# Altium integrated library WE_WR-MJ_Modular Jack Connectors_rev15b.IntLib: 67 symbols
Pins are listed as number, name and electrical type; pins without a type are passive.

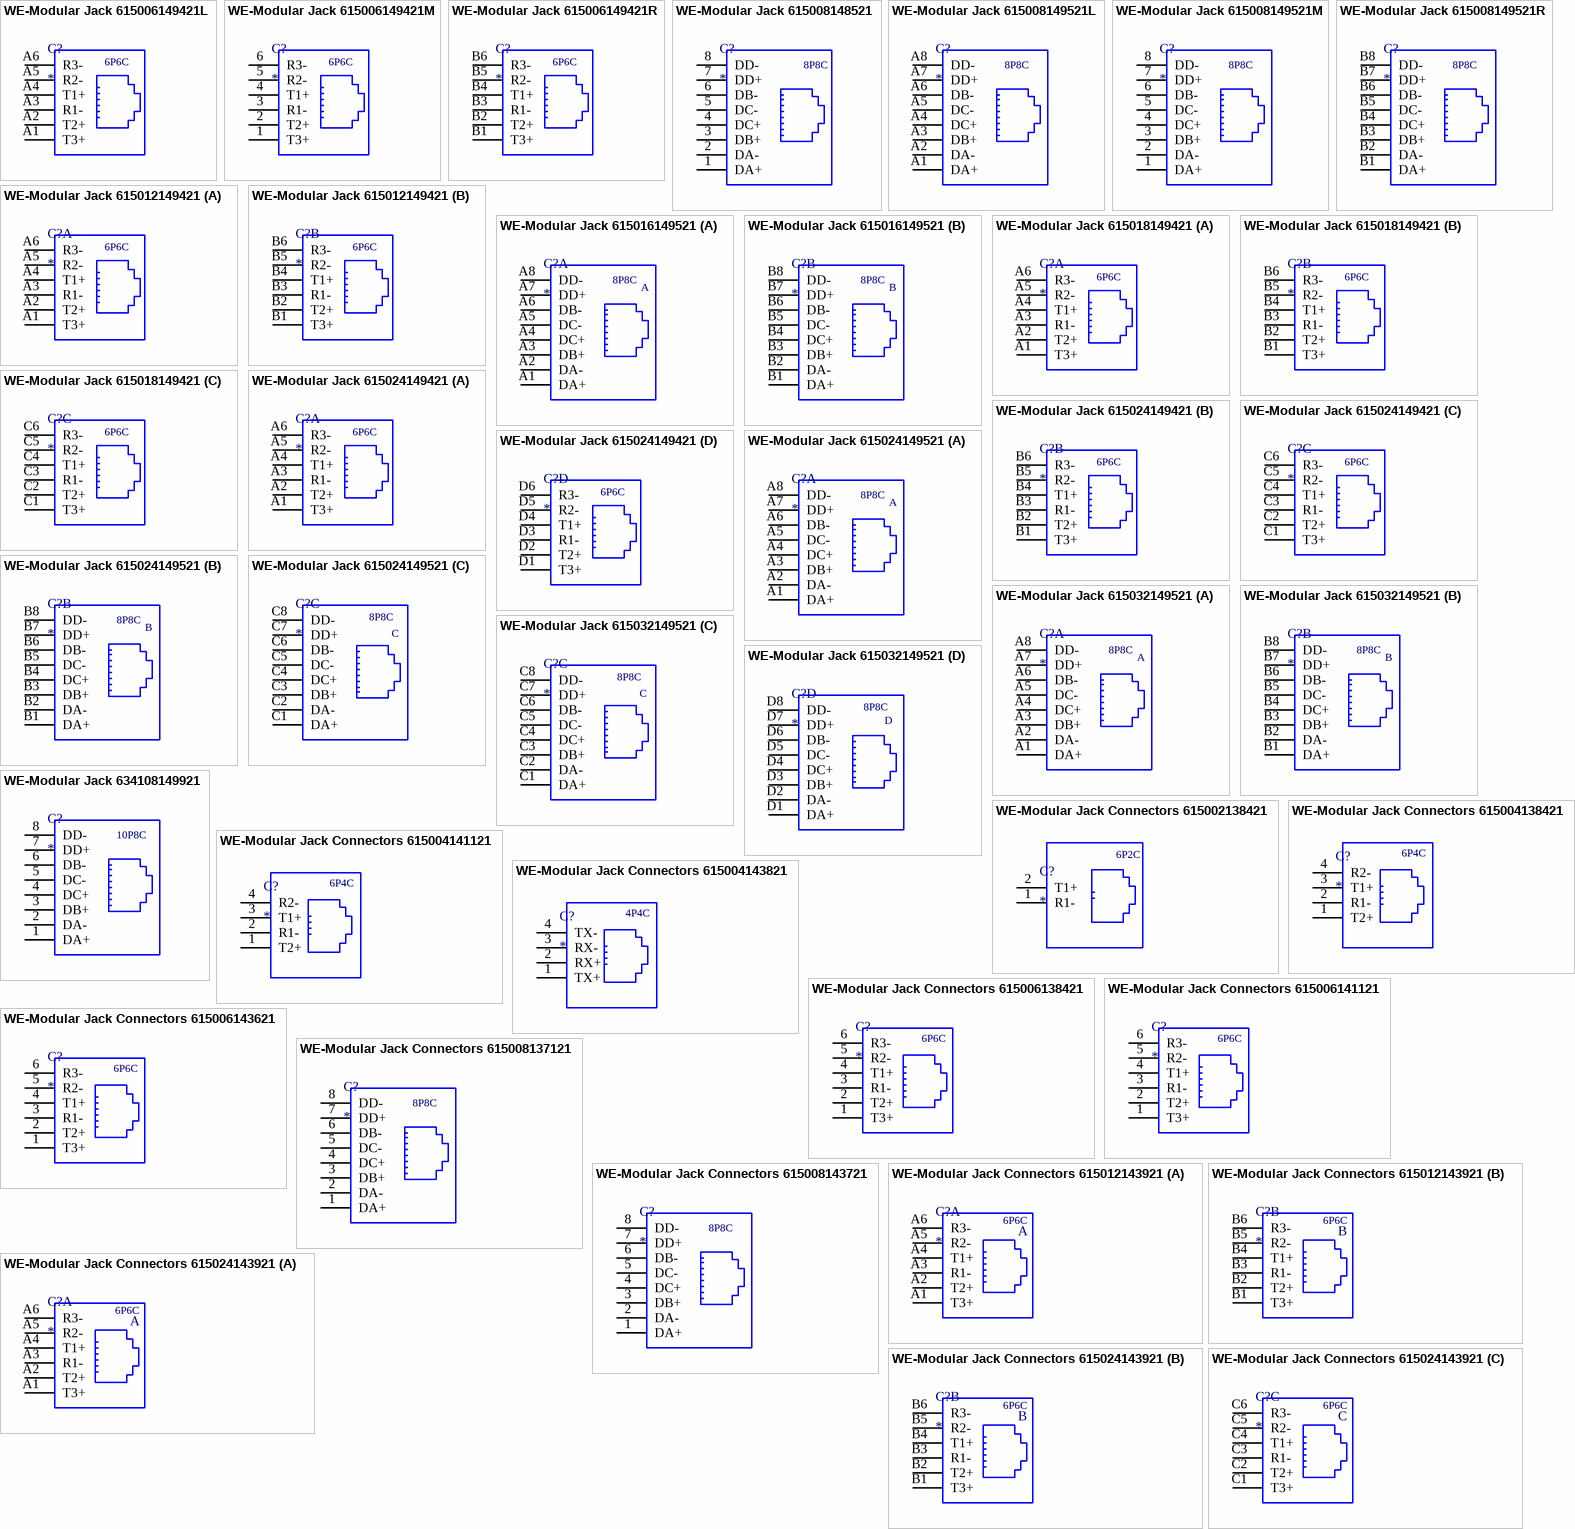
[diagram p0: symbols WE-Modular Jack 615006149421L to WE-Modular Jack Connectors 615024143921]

## WE-Modular Jack 615006149421L
designator C?
WR-MJ_Modular Jack_Tab UP_6P6C; Manufacturer: Würth Elektronik eiSos GmbH; partNo: 615006149421L; ComponentLink1 Description: Manufacturer; ComponentLink2 Description: Datasheet; NoPins: 6
footprint 615006149421L
pins: A1 T3+, A2 T2+, A3 R1-, A4 T1+, A5 R2-, A6 R3-

## WE-Modular Jack 615006149421M
designator C?
WR-MJ_Modular Jack_Tab UP_6P6C; Manufacturer: Würth Elektronik eiSos GmbH; partNo: 615006149421M; ComponentLink1 Description: Manufacturer; ComponentLink2 Description: Datasheet; NoPins: 6
footprint 615006149421M
pins: 1 T3+, 2 T2+, 3 R1-, 4 T1+, 5 R2-, 6 R3-

## WE-Modular Jack 615006149421R
designator C?
WR-MJ_Modular Jack_Tab UP_6P6C; Manufacturer: Würth Elektronik eiSos GmbH; partNo: 615006149421R; ComponentLink1 Description: Manufacturer; ComponentLink2 Description: Datasheet; NoPins: 6
footprint 615006149421R
pins: B1 T3+, B2 T2+, B3 R1-, B4 T1+, B5 R2-, B6 R3-

## WE-Modular Jack 615008148521
designator C?
WR-MJ_Modular Jacks_Plastic_8P8C; Manufacturer: Würth Elektronik eiSos GmbH; partNo: 615008148521; ComponentLink1 Description: Manufacturer; ComponentLink2 Description: Datasheet; NoPins: 8
footprint 615008148521
pins: 1 DA+, 2 DA-, 3 DB+, 4 DC+, 5 DC-, 6 DB-, 7 DD+, 8 DD-

## WE-Modular Jack 615008149521L
designator C?
WR-MJ_Modular Jack_Tab UP_8P8C; Manufacturer: Würth Elektronik eiSos GmbH; partNo: 615008149521L; ComponentLink1 Description: Manufacturer; ComponentLink2 Description: Datasheet; NoPins: 8
footprint 615008149521L
pins: A1 DA+, A2 DA-, A3 DB+, A4 DC+, A5 DC-, A6 DB-, A7 DD+, A8 DD-

## WE-Modular Jack 615008149521M
designator C?
WR-MJ_Modular Jack_Tab UP_8P8C; Manufacturer: Würth Elektronik eiSos GmbH; partNo: 615008149521M; ComponentLink1 Description: Manufacturer; ComponentLink2 Description: Datasheet; NoPins: 8
footprint 615008149521M
pins: 1 DA+, 2 DA-, 3 DB+, 4 DC+, 5 DC-, 6 DB-, 7 DD+, 8 DD-

## WE-Modular Jack 615008149521R
designator C?
WR-MJ_Modular Jack_Tab UP_8P8C; Manufacturer: Würth Elektronik eiSos GmbH; partNo: 615008149521R; ComponentLink1 Description: Manufacturer; ComponentLink2 Description: Datasheet; NoPins: 8
footprint 615008149521R
pins: B1 DA+, B2 DA-, B3 DB+, B4 DC+, B5 DC-, B6 DB-, B7 DD+, B8 DD-

## WE-Modular Jack 615012149421
designator C?
WR-MJ_Modular Jack_Tab UP_6P6C; Manufacturer: Würth Elektronik eiSos GmbH; partNo: 615012149421; ComponentLink1 Description: Manufacturer; ComponentLink2 Description: Datasheet; NoPins: 12
footprint 615012149421
part A pins: A1 T3+, A2 T2+, A3 R1-, A4 T1+, A5 R2-, A6 R3-
part B pins: B1 T3+, B2 T2+, B3 R1-, B4 T1+, B5 R2-, B6 R3-

## WE-Modular Jack 615016149521
designator C?
WR-MJ_Modular Jack_Tab UP_8P8C; Manufacturer: Würth Elektronik eiSos GmbH; partNo: 615016149521; ComponentLink1 Description: Manufacturer; ComponentLink2 Description: Datasheet; NoPins: 16
footprint 615016149521
part A pins: A1 DA+, A2 DA-, A3 DB+, A4 DC+, A5 DC-, A6 DB-, A7 DD+, A8 DD-
part B pins: B1 DA+, B2 DA-, B3 DB+, B4 DC+, B5 DC-, B6 DB-, B7 DD+, B8 DD-

## WE-Modular Jack 615018149421
designator C?
WR-MJ_Modular Jack_Tab UP_6P6C; Manufacturer: Würth Elektronik eiSos GmbH; partNo: 615018149421; ComponentLink1 Description: Manufacturer; ComponentLink2 Description: Datasheet; NoPins: 18
footprint 615018149421
part A pins: A1 T3+, A2 T2+, A3 R1-, A4 T1+, A5 R2-, A6 R3-
part B pins: B1 T3+, B2 T2+, B3 R1-, B4 T1+, B5 R2-, B6 R3-
part C pins: C1 T3+, C2 T2+, C3 R1-, C4 T1+, C5 R2-, C6 R3-

## WE-Modular Jack 615024149421
designator C?
WR-MJ_Modular Jack_Tab UP_6P6C; Manufacturer: Würth Elektronik eiSos GmbH; partNo: 615024149421; ComponentLink1 Description: Manufacturer; ComponentLink2 Description: Datasheet; NoPins: 24
footprint 615024149421
part A pins: A1 T3+, A2 T2+, A3 R1-, A4 T1+, A5 R2-, A6 R3-
part B pins: B1 T3+, B2 T2+, B3 R1-, B4 T1+, B5 R2-, B6 R3-
part C pins: C1 T3+, C2 T2+, C3 R1-, C4 T1+, C5 R2-, C6 R3-
part D pins: D1 T3+, D2 T2+, D3 R1-, D4 T1+, D5 R2-, D6 R3-

## WE-Modular Jack 615024149521
designator C?
WR-MJ_Modular Jack_Tab UP_8P8C; Manufacturer: Würth Elektronik eiSos GmbH; partNo: 615024149521; ComponentLink1 Description: Manufacturer; ComponentLink2 Description: Datasheet; NoPins: 24
footprint 615024149521
part A pins: A1 DA+, A2 DA-, A3 DB+, A4 DC+, A5 DC-, A6 DB-, A7 DD+, A8 DD-
part B pins: B1 DA+, B2 DA-, B3 DB+, B4 DC+, B5 DC-, B6 DB-, B7 DD+, B8 DD-
part C pins: C1 DA+, C2 DA-, C3 DB+, C4 DC+, C5 DC-, C6 DB-, C7 DD+, C8 DD-

## WE-Modular Jack 615032149521
designator C?
WR-MJ_Modular Jack_Tab UP_8P8C; Manufacturer: Würth Elektronik eiSos GmbH; partNo: 615032149521; ComponentLink1 Description: Manufacturer; ComponentLink2 Description: Datasheet; NoPins: 32
footprint 615032149521
part A pins: A1 DA+, A2 DA-, A3 DB+, A4 DC+, A5 DC-, A6 DB-, A7 DD+, A8 DD-
part B pins: B1 DA+, B2 DA-, B3 DB+, B4 DC+, B5 DC-, B6 DB-, B7 DD+, B8 DD-
part C pins: C1 DA+, C2 DA-, C3 DB+, C4 DC+, C5 DC-, C6 DB-, C7 DD+, C8 DD-
part D pins: D1 DA+, D2 DA-, D3 DB+, D4 DC+, D5 DC-, D6 DB-, D7 DD+, D8 DD-

## WE-Modular Jack 634108149921
designator C?
WR-MJ_Modular Jack_Tab DOWN_10P8C; Manufacturer: Würth Elektronik eiSos GmbH; partNo: 634108149921; ComponentLink1 Description: Manufacturer; ComponentLink2 Description: Datasheet; NoPins: 8
footprint 634108149921
pins: 1 DA+, 2 DA-, 3 DB+, 4 DC+, 5 DC-, 6 DB-, 7 DD+, 8 DD-

## WE-Modular Jack Connectors 615002138421
designator C?
WR-COM Modular Jack Horizontal Plastic 1x1 TH    6P2C Tab Up; Manufacturer: Würth Elektronik eiSos GmbH; partNo: 615002138421; ComponentLink1 Description: Manufacturer; ComponentLink2 Description: Datasheet; NoPins: 2
footprint 615002138421
pins: 1 R1-, 2 T1+

## WE-Modular Jack Connectors 615004138421
designator C?
WR-COM Modular Jack Horizontal Plastic 1x1 TH    6P4C Tab Up; Manufacturer: Würth Elektronik eiSos GmbH; partNo: 615004138421; ComponentLink1 Description: Manufacturer; ComponentLink2 Description: Datasheet; NoPins: 4
footprint 615004138421
pins: 1 T2+, 2 R1-, 3 T1+, 4 R2-

## WE-Modular Jack Connectors 615004141121
designator C?
WR-COM Modular Jack Horizontal Plastic 1x1 TH    6P4C Tab Down; Manufacturer: Würth Elektronik eiSos GmbH; partNo: 615004141121; ComponentLink1 Description: Manufacturer; ComponentLink2 Description: Datasheet; NoPins: 4
footprint 615004141121
pins: 1 T2+, 2 R1-, 3 T1+, 4 R2-

## WE-Modular Jack Connectors 615004143821
designator C?
WR-COM Modular Jack Horizontal Plastic 1x1 TH    4P4C Tab Up; Manufacturer: Würth Elektronik eiSos GmbH; partNo: 615004143821; ComponentLink1 Description: Manufacturer; ComponentLink2 Description: Datasheet; NoPins: 4
footprint 615004143821
pins: 1 TX+, 2 RX+, 3 RX-, 4 TX-

## WE-Modular Jack Connectors 615006138421
designator C?
WR-COM Modular Jack Horizontal Plastic 1x1 TH  6P6C Tab Up; Manufacturer: Würth Elektronik eiSos GmbH; partNo: 615006138421; ComponentLink1 Description: Manufacturer; ComponentLink2 Description: Datasheet; NoPins: 6
footprint 615006138421
pins: 1 T3+, 2 T2+, 3 R1-, 4 T1+, 5 R2-, 6 R3-

## WE-Modular Jack Connectors 615006141121
designator C?
WR-COM Modular Jack Horizontal Plastic 1x1 TH    6P6C Tab Down; Manufacturer: Würth Elektronik eiSos GmbH; partNo: 615006141121; ComponentLink1 Description: Manufacturer; ComponentLink2 Description: Datasheet; NoPins: 6
footprint 615006141121
pins: 1 T3+, 2 T2+, 3 R1-, 4 T1+, 5 R2-, 6 R3-

## WE-Modular Jack Connectors 615006143621
designator C?
WR-COM Modular Jack Horizontal Plastic 1x1 TH    6P6C Tab Down; Manufacturer: Würth Elektronik eiSos GmbH; partNo: 615006143621; ComponentLink1 Description: Manufacturer; ComponentLink2 Description: Datasheet; NoPins: 6
footprint 615006143621
pins: 1 T3+, 2 T2+, 3 R1-, 4 T1+, 5 R2-, 6 R3-

## WE-Modular Jack Connectors 615008137121
designator C?
WR-COM Modular Jack RJ45 Horizontal Tab down; Manufacturer: Würth Elektronik eiSos GmbH; partNo: 615008137121; ComponentLink1 Description: Manufacturer; ComponentLink2 Description: Datasheet; NoPins: 8
footprint 615008137121
pins: 1 DA+, 2 DA-, 3 DB+, 4 DC+, 5 DC-, 6 DB-, 7 DD+, 8 DD-

## WE-Modular Jack Connectors 615008143721
designator C?
WR-COM Modular Jack Horizontal Plastic 1x1 TH    8P8C Tab Down; Manufacturer: Würth Elektronik eiSos GmbH; partNo: 615008143721; ComponentLink1 Description: Manufacturer; ComponentLink2 Description: Datasheet; NoPins: 8
footprint 615008143721
pins: 1 DA+, 2 DA-, 3 DB+, 4 DC+, 5 DC-, 6 DB-, 7 DD+, 8 DD-

## WE-Modular Jack Connectors 615012143921
designator C?
WR-COM Modular Jack Horizontal Plastic 1x2 TH    6P6C Tab Up; Manufacturer: Würth Elektronik eiSos GmbH; partNo: 615012143921; ComponentLink1 Description: Manufacturer; ComponentLink2 Description: Datasheet; NoPins: 12
footprint 615012143921
part A pins: A1 T3+, A2 T2+, A3 R1-, A4 T1+, A5 R2-, A6 R3-
part B pins: B1 T3+, B2 T2+, B3 R1-, B4 T1+, B5 R2-, B6 R3-

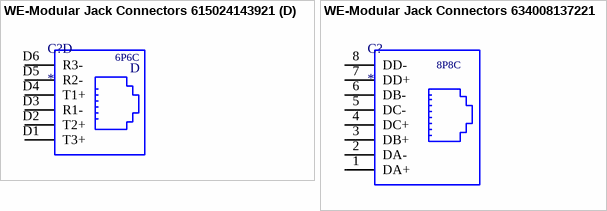
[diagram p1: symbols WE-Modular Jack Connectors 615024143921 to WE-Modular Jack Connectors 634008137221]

## WE-Modular Jack Connectors 615024143921
designator C?
WR-COM Modular Jack Horizontal Plastic 1x4 TH    6P6C Tab Up; Manufacturer: Würth Elektronik eiSos GmbH; partNo: 615024143921; ComponentLink1 Description: Manufacturer; ComponentLink2 Description: Datasheet; NoPins: 24
footprint 615024143921
part A pins: A1 T3+, A2 T2+, A3 R1-, A4 T1+, A5 R2-, A6 R3-
part B pins: B1 T3+, B2 T2+, B3 R1-, B4 T1+, B5 R2-, B6 R3-
part C pins: C1 T3+, C2 T2+, C3 R1-, C4 T1+, C5 R2-, C6 R3-
part D pins: D1 T3+, D2 T2+, D3 R1-, D4 T1+, D5 R2-, D6 R3-

## WE-Modular Jack Connectors 634008137221
designator C?
WR-COM Modular Jack RJ45 Horizontal SMT Tab down; Manufacturer: Würth Elektronik eiSos GmbH; partNo: 634008137221; ComponentLink1 Description: Manufacturer; ComponentLink2 Description: Datasheet; NoPins: 8
footprint 634008137221
pins: 1 DA+, 2 DA-, 3 DB+, 4 DC+, 5 DC-, 6 DB-, 7 DD+, 8 DD-


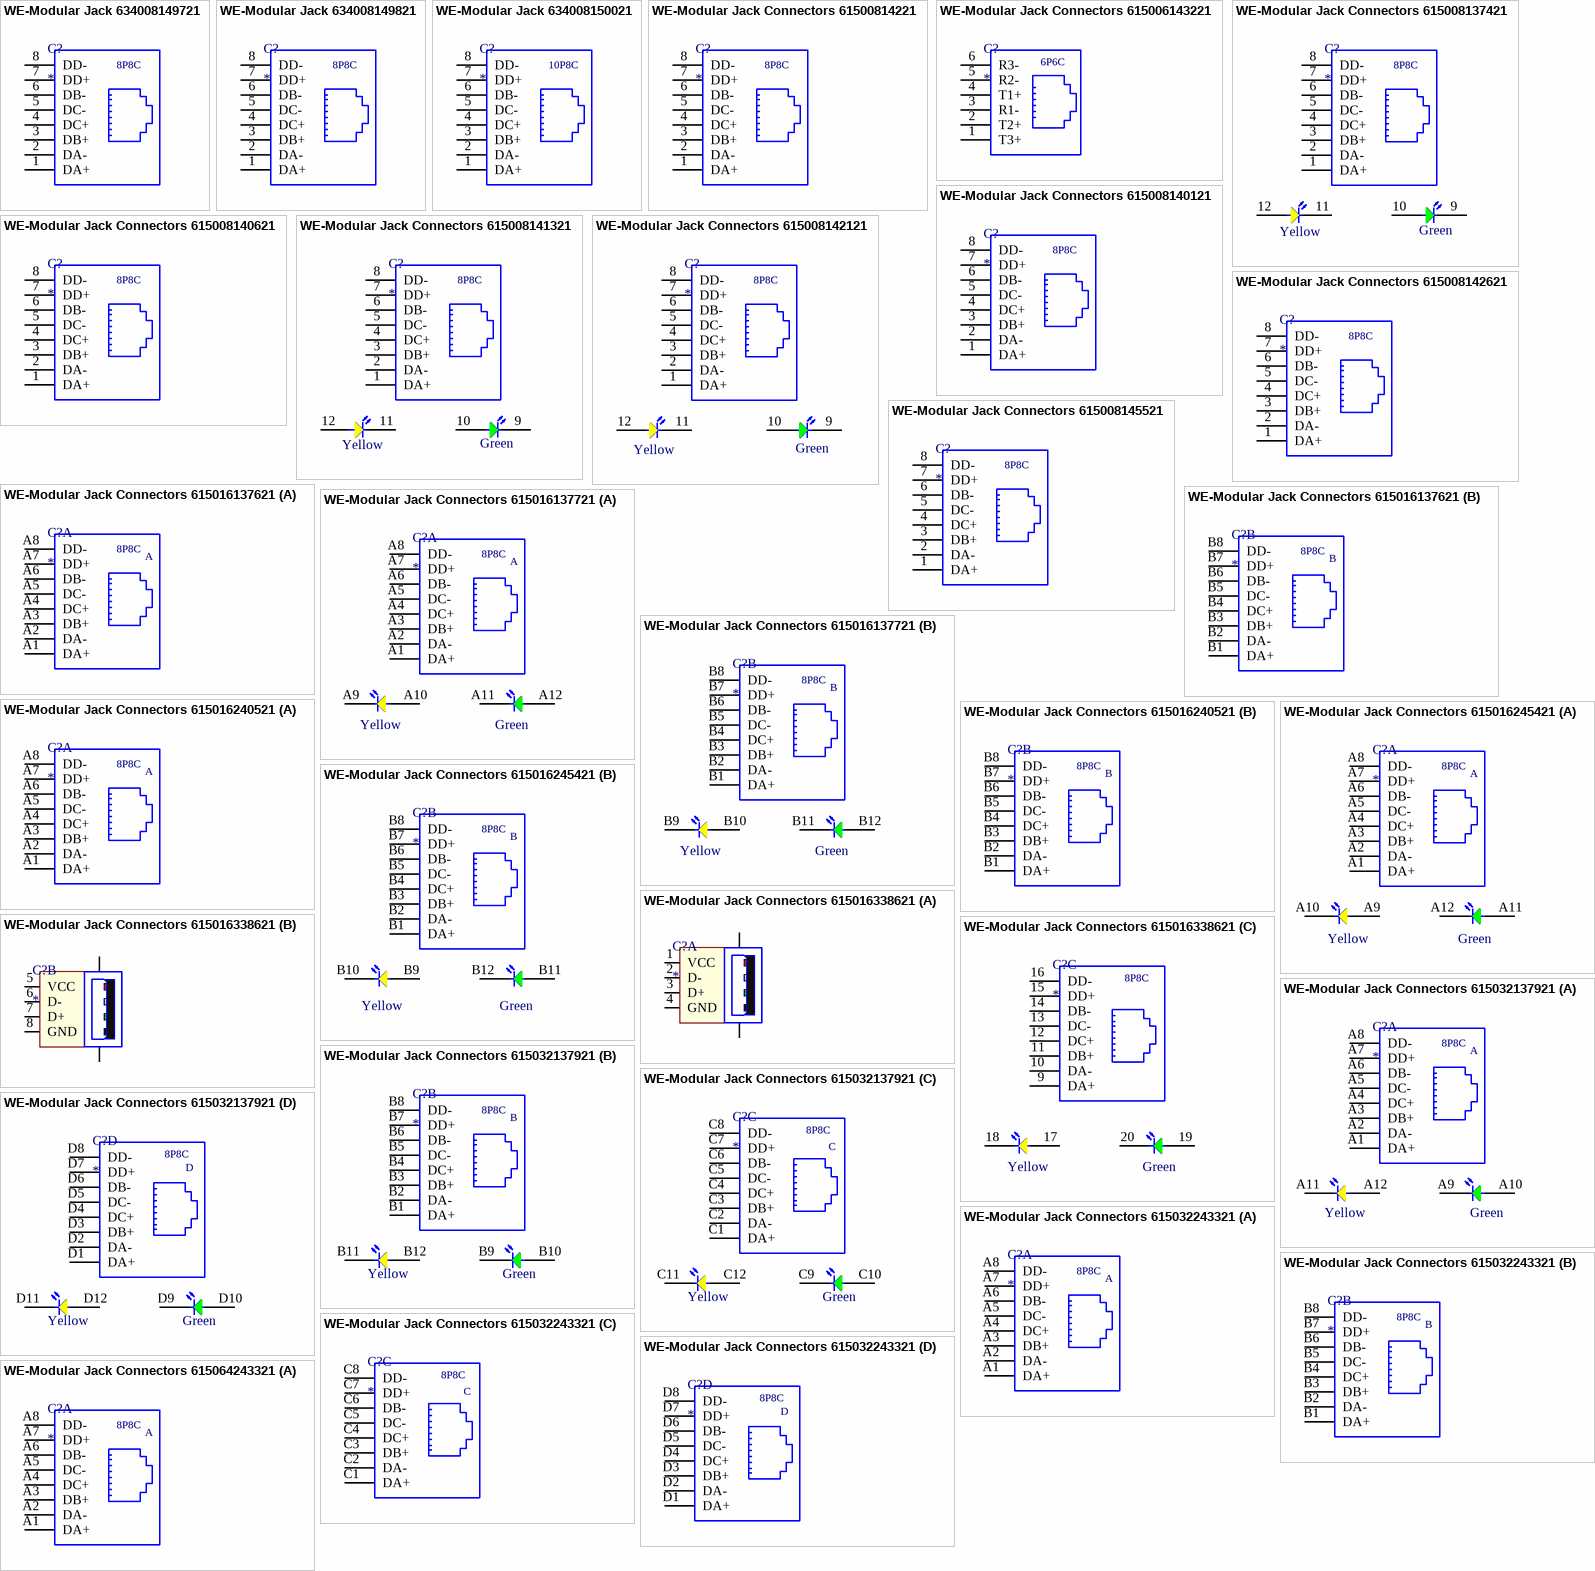
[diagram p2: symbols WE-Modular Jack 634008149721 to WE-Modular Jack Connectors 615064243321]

## WE-Modular Jack 634008149721
designator C?
WR-MJ_Modular Jack_Tab UP_8P8C; Manufacturer: Würth Elektronik eiSos GmbH; partNo: 634008149721; ComponentLink1 Description: Manufacturer; ComponentLink2 Description: Datasheet; NoPins: 8
footprint 634008149721
pins: 1 DA+, 2 DA-, 3 DB+, 4 DC+, 5 DC-, 6 DB-, 7 DD+, 8 DD-

## WE-Modular Jack 634008149821
designator C?
WR-MJ_Modular Jack_Tab UP_8P8C; Manufacturer: Würth Elektronik eiSos GmbH; partNo: 634008149821; ComponentLink1 Description: Manufacturer; ComponentLink2 Description: Datasheet; NoPins: 8
footprint 634008149821
pins: 1 DA+, 2 DA-, 3 DB+, 4 DC+, 5 DC-, 6 DB-, 7 DD+, 8 DD-

## WE-Modular Jack 634008150021
designator C?
WR-MJ_Modular Jack_Tab DOWN_10P8C; Manufacturer: Würth Elektronik eiSos GmbH; partNo: 634008150021; ComponentLink1 Description: Manufacturer; ComponentLink2 Description: Datasheet; NoPins: 8
footprint 634008150021
pins: 1 DA+, 2 DA-, 3 DB+, 4 DC+, 5 DC-, 6 DB-, 7 DD+, 8 DD-

## WE-Modular Jack Connectors 61500814221
designator C?
WR-COM Modular Jack RJ45 Horizontal  Shielded  Tab down; Manufacturer: Würth Elektronik eiSos GmbH; partNo: 61500814221; ComponentLink1 Description: Manufacturer; ComponentLink2 Description: Datasheet; NoPins: 8
footprint 61500814221
pins: 1 DA+, 2 DA-, 3 DB+, 4 DC+, 5 DC-, 6 DB-, 7 DD+, 8 DD-

## WE-Modular Jack Connectors 615006143221
designator C?
WR-COM Modular Jack Horizontal Shielded 1x1 TH    6P6C Tab Up; Manufacturer: Würth Elektronik eiSos GmbH; partNo: 615006143221; ComponentLink1 Description: Manufacturer; ComponentLink2 Description: Datasheet; NoPins: 6
footprint 615006143221
pins: 1 T3+, 2 T2+, 3 R1-, 4 T1+, 5 R2-, 6 R3-

## WE-Modular Jack Connectors 615008137421
designator C?
WR-COM Modular Jack RJ45 Horizontal  Shielded  With LED With EMI panel ground Tab up - Left yellow - Right green; Manufacturer: Würth Elektronik eiSos GmbH; partNo: 615008137421; ComponentLink1 Description: Manufacturer; ComponentLink2 Description: Datasheet; NoPins: 12
footprint 615008137421
pins: 1 DA+, 2 DA-, 3 DB+, 4 DC+, 5 DC-, 6 DB-, 7 DD+, 8 DD-, 9, 10, 11, 12

## WE-Modular Jack Connectors 615008140121
designator C?
WR-COM Modular Jack Horizontal Shielded 1x1 TH   3,05mm 8P8C Tab Down; Manufacturer: Würth Elektronik eiSos GmbH; partNo: 615008140121; ComponentLink1 Description: Manufacturer; ComponentLink2 Description: Datasheet; NoPins: 8
footprint 615008140121
pins: 1 DA+, 2 DA-, 3 DB+, 4 DC+, 5 DC-, 6 DB-, 7 DD+, 8 DD-

## WE-Modular Jack Connectors 615008140621
designator C?
WR-COM Modular Jack Horizontal Shielded 1x1 TH  EMI  fingers  8P8C Tab Up; Manufacturer: Würth Elektronik eiSos GmbH; partNo: 615008140621; ComponentLink1 Description: Manufacturer; ComponentLink2 Description: Datasheet; NoPins: 8
footprint 615008140621
pins: 1 DA+, 2 DA-, 3 DB+, 4 DC+, 5 DC-, 6 DB-, 7 DD+, 8 DD-

## WE-Modular Jack Connectors 615008141321
designator C?
WR-COM Modular Jack Horizontal Shielded 1x1 TH LED 2x Bipolar Green/Yellow Green=Fw EMI  fingers  8P8C Tab Up; Manufacturer: Würth Elektronik eiSos GmbH; partNo: 615008141321; ComponentLink1 Description: Manufacturer; ComponentLink2 Description: Datasheet; NoPins: 12
footprint 615008141321
pins: 1 DA+, 2 DA-, 3 DB+, 4 DC+, 5 DC-, 6 DB-, 7 DD+, 8 DD-, 9, 10, 11, 12

## WE-Modular Jack Connectors 615008142121
designator C?
WR-COM Modular Jack Horizontal Shielded 1x1 TH LED 2x Bipolar Yellow/Green Yellow=Fw EMI  fingers  8P8C Tab Up; Manufacturer: Würth Elektronik eiSos GmbH; partNo: 615008142121; ComponentLink1 Description: Manufacturer; ComponentLink2 Description: Datasheet; NoPins: 12
footprint 615008142121
pins: 1 DA+, 2 DA-, 3 DB+, 4 DC+, 5 DC-, 6 DB-, 7 DD+, 8 DD-, 9, 10, 11, 12

## WE-Modular Jack Connectors 615008142621
designator C?
WR-COM Modular Jack Horizontal Shielded 1x1 TH   rear EMI PCB post 8P8C Tab Down; Manufacturer: Würth Elektronik eiSos GmbH; partNo: 615008142621; ComponentLink1 Description: Manufacturer; ComponentLink2 Description: Datasheet; NoPins: 8
footprint 615008142621
pins: 1 DA+, 2 DA-, 3 DB+, 4 DC+, 5 DC-, 6 DB-, 7 DD+, 8 DD-

## WE-Modular Jack Connectors 615008145521
designator C?
WR-COM Modular Jack Cat 5e - Horizontal Shielded - 1x1 - TH -  EMI  fingers  - 8P8C - Tab Down; Manufacturer: Würth Elektronik eiSos GmbH; partNo: 615008145521; ComponentLink1 Description: Manufacturer; ComponentLink2 Description: Datasheet; NoPins: 8
footprint 615008145521
pins: 1 DA+, 2 DA-, 3 DB+, 4 DC+, 5 DC-, 6 DB-, 7 DD+, 8 DD-

## WE-Modular Jack Connectors 615016137621
designator C?
WR-COM Modular Jack RJ45 Horizontal Dual port Shielded Tab down; Manufacturer: Würth Elektronik eiSos GmbH; partNo: 615016137621; ComponentLink1 Description: Manufacturer; ComponentLink2 Description: Datasheet; NoPins: 16
footprint 615016137621
part A pins: A1 DA+, A2 DA-, A3 DB+, A4 DC+, A5 DC-, A6 DB-, A7 DD+, A8 DD-
part B pins: B1 DA+, B2 DA-, B3 DB+, B4 DC+, B5 DC-, B6 DB-, B7 DD+, B8 DD-

## WE-Modular Jack Connectors 615016137721
designator C?
WR-COM Modular Jack RJ45 Horizontal Dual port Shielded  With LED With EMI panel ground Tab up - left yellow - right green; Manufacturer: Würth Elektronik eiSos GmbH; partNo: 615016137721; ComponentLink1 Description: Manufacturer; ComponentLink2 Description: Datasheet; NoPins: 24
footprint 615016137721
part A pins: A1 DA+, A2 DA-, A3 DB+, A4 DC+, A5 DC-, A6 DB-, A7 DD+, A8 DD-, A9, A10, A11, A12
part B pins: B1 DA+, B2 DA-, B3 DB+, B4 DC+, B5 DC-, B6 DB-, B7 DD+, B8 DD-, B9, B10, B11, B12

## WE-Modular Jack Connectors 615016240521
designator C?
WR-COM Modular Jack Horizontal Shielded 2x1 TH  EMI  fingers  8P8C Tab Down & Up; Manufacturer: Würth Elektronik eiSos GmbH; partNo: 615016240521; ComponentLink1 Description: Manufacturer; ComponentLink2 Description: Datasheet; NoPins: 16
footprint 615016240521
part A pins: A1 DA+, A2 DA-, A3 DB+, A4 DC+, A5 DC-, A6 DB-, A7 DD+, A8 DD-
part B pins: B1 DA+, B2 DA-, B3 DB+, B4 DC+, B5 DC-, B6 DB-, B7 DD+, B8 DD-

## WE-Modular Jack Connectors 615016245421
designator C?
WR-COM Modular Jack Horizontal Shielded 2x1 TH  EMI  fingers with LED (Yellow=left / Green=right) 8P8C Tab Down & Up; Manufacturer: Würth Elektronik eiSos GmbH; partNo: 615016245421; ComponentLink1 Description: Manufacturer; ComponentLink2 Description: Datasheet; NoPins: 24
footprint 615016245421
part A pins: A1 DA+, A2 DA-, A3 DB+, A4 DC+, A5 DC-, A6 DB-, A7 DD+, A8 DD-, A9, A10, A11, A12
part B pins: B1 DA+, B2 DA-, B3 DB+, B4 DC+, B5 DC-, B6 DB-, B7 DD+, B8 DD-, B9, B10, B11, B12

## WE-Modular Jack Connectors 615016338621
designator C?
WR-COM Modular Jack RJ45 + dual USB stacked Horizontal Tab up; Manufacturer: Würth Elektronik eiSos GmbH; partNo: 615016338621; ComponentLink1 Description: Manufacturer; ComponentLink2 Description: Datasheet; NoPins: 20
footprint 615016338621
part A pins: 1 VCC, 2 D-, 3 D+, 4 GND, Z1 Shield, Z2 Shield
part B pins: 5 VCC, 6 D-, 7 D+, 8 GND, Z1 Shield, Z2 Shield
part C pins: 9 DA+, 10 DA-, 11 DB+, 12 DC+, 13 DC-, 14 DB-, 15 DD+, 16 DD-, 17, 18, 19, 20

## WE-Modular Jack Connectors 615032137921
designator C?
WR-COM Modular Jack RJ45 Horizontal Ganged 4 ports Shielded  With LED With EMI panel ground Tab up - left yellow - right green; Manufacturer: Würth Elektronik eiSos GmbH; partNo: 615032137921; ComponentLink1 Description: Manufacturer; ComponentLink2 Description: Datasheet; NoPins: 48
footprint 615032137921
part A pins: A1 DA+, A2 DA-, A3 DB+, A4 DC+, A5 DC-, A6 DB-, A7 DD+, A8 DD-, A9, A10, A11, A12
part B pins: B1 DA+, B2 DA-, B3 DB+, B4 DC+, B5 DC-, B6 DB-, B7 DD+, B8 DD-, B9, B10, B11, B12
part C pins: C1 DA+, C2 DA-, C3 DB+, C4 DC+, C5 DC-, C6 DB-, C7 DD+, C8 DD-, C9, C10, C11, C12
part D pins: D1 DA+, D2 DA-, D3 DB+, D4 DC+, D5 DC-, D6 DB-, D7 DD+, D8 DD-, D9, D10, D11, D12

## WE-Modular Jack Connectors 615032243321
designator C?
WR-COM Modular Jack Horizontal Shielded 2x2 TH  EMI  fingers  8P8C Tab Down & Up; Manufacturer: Würth Elektronik eiSos GmbH; partNo: 615032243321; ComponentLink1 Description: Manufacturer; ComponentLink2 Description: Datasheet; NoPins: 32
footprint 615032243321
part A pins: A1 DA+, A2 DA-, A3 DB+, A4 DC+, A5 DC-, A6 DB-, A7 DD+, A8 DD-
part B pins: B1 DA+, B2 DA-, B3 DB+, B4 DC+, B5 DC-, B6 DB-, B7 DD+, B8 DD-
part C pins: C1 DA+, C2 DA-, C3 DB+, C4 DC+, C5 DC-, C6 DB-, C7 DD+, C8 DD-
part D pins: D1 DA+, D2 DA-, D3 DB+, D4 DC+, D5 DC-, D6 DB-, D7 DD+, D8 DD-

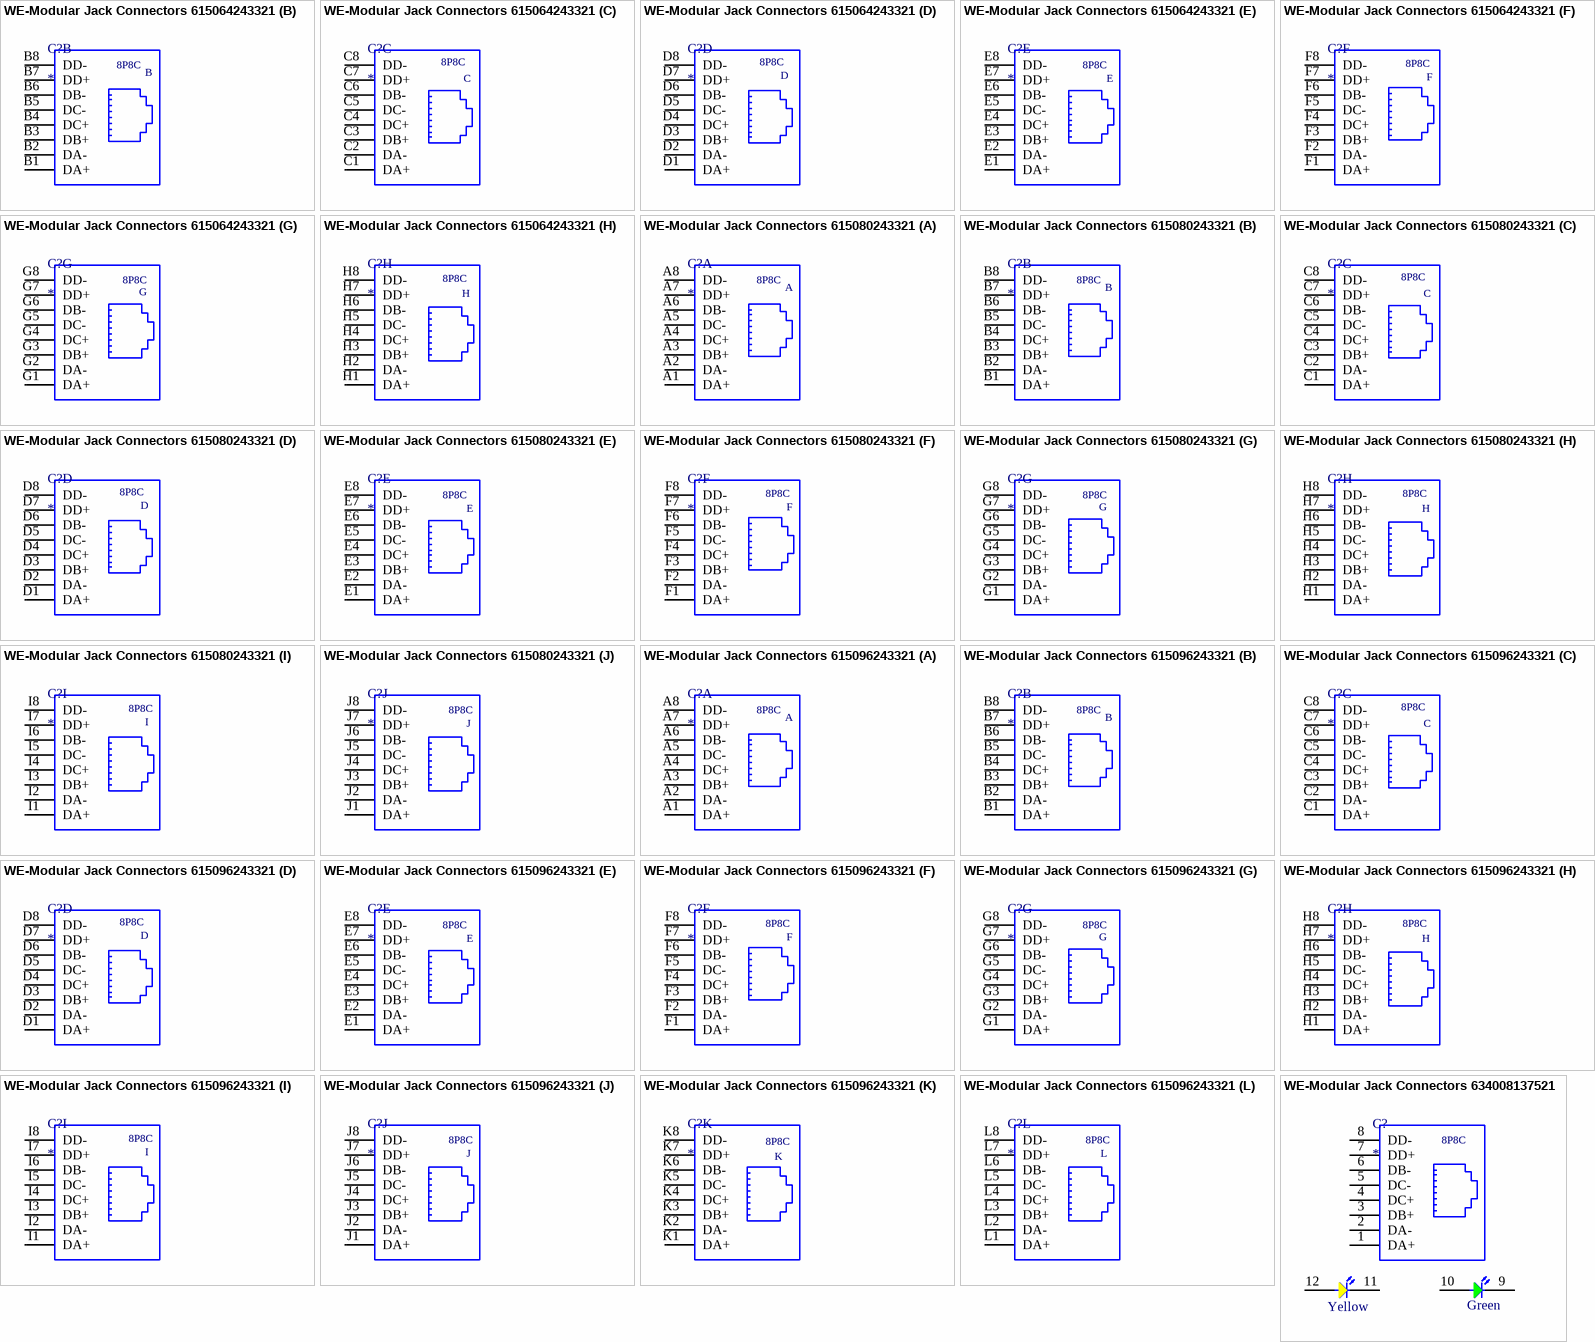
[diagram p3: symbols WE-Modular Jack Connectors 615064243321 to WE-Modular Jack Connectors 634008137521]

## WE-Modular Jack Connectors 615064243321
designator C?
WR-COM Modular Jack Horizontal Shielded 2x4 TH  EMI  fingers  8P8C Tab Down & Up; Manufacturer: Würth Elektronik eiSos GmbH; partNo: 615064243321; ComponentLink1 Description: Manufacturer; ComponentLink2 Description: Datasheet; NoPins: 64
footprint 615064243321
part A pins: A1 DA+, A2 DA-, A3 DB+, A4 DC+, A5 DC-, A6 DB-, A7 DD+, A8 DD-
part B pins: B1 DA+, B2 DA-, B3 DB+, B4 DC+, B5 DC-, B6 DB-, B7 DD+, B8 DD-
part C pins: C1 DA+, C2 DA-, C3 DB+, C4 DC+, C5 DC-, C6 DB-, C7 DD+, C8 DD-
part D pins: D1 DA+, D2 DA-, D3 DB+, D4 DC+, D5 DC-, D6 DB-, D7 DD+, D8 DD-
part E pins: E1 DA+, E2 DA-, E3 DB+, E4 DC+, E5 DC-, E6 DB-, E7 DD+, E8 DD-
part F pins: F1 DA+, F2 DA-, F3 DB+, F4 DC+, F5 DC-, F6 DB-, F7 DD+, F8 DD-
part G pins: G1 DA+, G2 DA-, G3 DB+, G4 DC+, G5 DC-, G6 DB-, G7 DD+, G8 DD-
part H pins: H1 DA+, H2 DA-, H3 DB+, H4 DC+, H5 DC-, H6 DB-, H7 DD+, H8 DD-

## WE-Modular Jack Connectors 615080243321
designator C?
WR-COM Modular Jack Horizontal Shielded 2x5 TH  EMI  fingers  8P8C Tab Down & Up; Manufacturer: Würth Elektronik eiSos GmbH; partNo: 615080243321; ComponentLink1 Description: Manufacturer; ComponentLink2 Description: Datasheet; NoPins: 80
footprint 615080243321
part A pins: A1 DA+, A2 DA-, A3 DB+, A4 DC+, A5 DC-, A6 DB-, A7 DD+, A8 DD-
part B pins: B1 DA+, B2 DA-, B3 DB+, B4 DC+, B5 DC-, B6 DB-, B7 DD+, B8 DD-
part C pins: C1 DA+, C2 DA-, C3 DB+, C4 DC+, C5 DC-, C6 DB-, C7 DD+, C8 DD-
part D pins: D1 DA+, D2 DA-, D3 DB+, D4 DC+, D5 DC-, D6 DB-, D7 DD+, D8 DD-
part E pins: E1 DA+, E2 DA-, E3 DB+, E4 DC+, E5 DC-, E6 DB-, E7 DD+, E8 DD-
part F pins: F1 DA+, F2 DA-, F3 DB+, F4 DC+, F5 DC-, F6 DB-, F7 DD+, F8 DD-
part G pins: G1 DA+, G2 DA-, G3 DB+, G4 DC+, G5 DC-, G6 DB-, G7 DD+, G8 DD-
part H pins: H1 DA+, H2 DA-, H3 DB+, H4 DC+, H5 DC-, H6 DB-, H7 DD+, H8 DD-
part I pins: I1 DA+, I2 DA-, I3 DB+, I4 DC+, I5 DC-, I6 DB-, I7 DD+, I8 DD-
part J pins: J1 DA+, J2 DA-, J3 DB+, J4 DC+, J5 DC-, J6 DB-, J7 DD+, J8 DD-

## WE-Modular Jack Connectors 615096243321
designator C?
WR-COM Modular Jack Horizontal Shielded 2x6 TH  EMI  fingers  8P8C Tab Down & Up; Manufacturer: Würth Elektronik eiSos GmbH; partNo: 615096243321; ComponentLink1 Description: Manufacturer; ComponentLink2 Description: Datasheet; NoPins: 96
footprint 615096243321
part A pins: A1 DA+, A2 DA-, A3 DB+, A4 DC+, A5 DC-, A6 DB-, A7 DD+, A8 DD-
part B pins: B1 DA+, B2 DA-, B3 DB+, B4 DC+, B5 DC-, B6 DB-, B7 DD+, B8 DD-
part C pins: C1 DA+, C2 DA-, C3 DB+, C4 DC+, C5 DC-, C6 DB-, C7 DD+, C8 DD-
part D pins: D1 DA+, D2 DA-, D3 DB+, D4 DC+, D5 DC-, D6 DB-, D7 DD+, D8 DD-
part E pins: E1 DA+, E2 DA-, E3 DB+, E4 DC+, E5 DC-, E6 DB-, E7 DD+, E8 DD-
part F pins: F1 DA+, F2 DA-, F3 DB+, F4 DC+, F5 DC-, F6 DB-, F7 DD+, F8 DD-
part G pins: G1 DA+, G2 DA-, G3 DB+, G4 DC+, G5 DC-, G6 DB-, G7 DD+, G8 DD-
part H pins: H1 DA+, H2 DA-, H3 DB+, H4 DC+, H5 DC-, H6 DB-, H7 DD+, H8 DD-
part I pins: I1 DA+, I2 DA-, I3 DB+, I4 DC+, I5 DC-, I6 DB-, I7 DD+, I8 DD-
part J pins: J1 DA+, J2 DA-, J3 DB+, J4 DC+, J5 DC-, J6 DB-, J7 DD+, J8 DD-
part K pins: K1 DA+, K2 DA-, K3 DB+, K4 DC+, K5 DC-, K6 DB-, K7 DD+, K8 DD-
part L pins: L1 DA+, L2 DA-, L3 DB+, L4 DC+, L5 DC-, L6 DB-, L7 DD+, L8 DD-

## WE-Modular Jack Connectors 634008137521
designator C?
WR-COM Modular Jack RJ45 Horizontal  Shielded SMT With LED With EMI panel ground Tab up - Tray packaging; Manufacturer: Würth Elektronik eiSos GmbH; partNo: 634008137521; ComponentLink1 Description: Manufacturer; ComponentLink2 Description: Datasheet; NoPins: 12
footprint 634008137521
pins: 1 DA+, 2 DA-, 3 DB+, 4 DC+, 5 DC-, 6 DB-, 7 DD+, 8 DD-, 9, 10, 11, 12


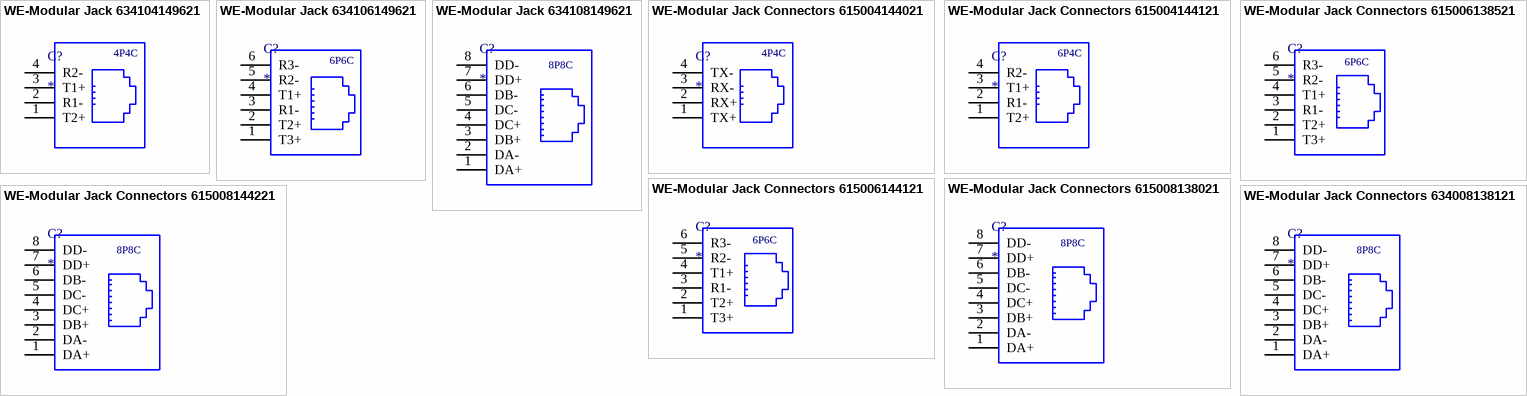
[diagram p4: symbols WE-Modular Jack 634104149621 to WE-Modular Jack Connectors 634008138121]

## WE-Modular Jack 634104149621
designator C?
WR-MJ_Modular Jack_Top Entry_4P4C; Manufacturer: Würth Elektronik eiSos GmbH; partNo: 634104149621; ComponentLink1 Description: Manufacturer; ComponentLink2 Description: Datasheet; NoPins: 4
footprint 634104149621
pins: 1 T2+, 2 R1-, 3 T1+, 4 R2-

## WE-Modular Jack 634106149621
designator C?
WR-MJ_Modular Jack_Top Entry_6P6C; Manufacturer: Würth Elektronik eiSos GmbH; partNo: 634106149621; ComponentLink1 Description: Manufacturer; ComponentLink2 Description: Datasheet; NoPins: 6
footprint 634106149621
pins: 1 T3+, 2 T2+, 3 R1-, 4 T1+, 5 R2-, 6 R3-

## WE-Modular Jack 634108149621
designator C?
WR-MJ_Modular Jack_Top Entry_8P8C; Manufacturer: Würth Elektronik eiSos GmbH; partNo: 634108149621; ComponentLink1 Description: Manufacturer; ComponentLink2 Description: Datasheet; NoPins: 8
footprint 634108149621
pins: 1 DA+, 2 DA-, 3 DB+, 4 DC+, 5 DC-, 6 DB-, 7 DD+, 8 DD-

## WE-Modular Jack Connectors 615004144021
designator C?
WR-COM Modular Jack Vertical Plastic 1x1 TH    4P4C; Manufacturer: Würth Elektronik eiSos GmbH; partNo: 615004144021; ComponentLink1 Description: Manufacturer; ComponentLink2 Description: Datasheet; NoPins: 4
footprint 615004144021 (Vertical Plastic 1x1 TH    4P4C)
pins: 1 TX+, 2 RX+, 3 RX-, 4 TX-

## WE-Modular Jack Connectors 615004144121
designator C?
WR-COM Modular Jack Vertical Plastic 1x1 TH    6P4C; Manufacturer: Würth Elektronik eiSos GmbH; partNo: 615004144121; ComponentLink1 Description: Manufacturer; ComponentLink2 Description: Datasheet; NoPins: 4
footprint 615004144121
pins: 1 T2+, 2 R1-, 3 T1+, 4 R2-

## WE-Modular Jack Connectors 615006138521
designator C?
WR-COM Modular Jack 6P6C vertical with ears; Manufacturer: Würth Elektronik eiSos GmbH; partNo: 615006138521; ComponentLink1 Description: Manufacturer; ComponentLink2 Description: Datasheet; NoPins: 6
footprint 615006138521
pins: 1 T3+, 2 T2+, 3 R1-, 4 T1+, 5 R2-, 6 R3-

## WE-Modular Jack Connectors 615006144121
designator C?
WR-COM Modular Jack Vertical Plastic 1x1 TH    6P6C; Manufacturer: Würth Elektronik eiSos GmbH; partNo: 615006144121; ComponentLink1 Description: Manufacturer; ComponentLink2 Description: Datasheet; NoPins: 6
footprint 615006144121
pins: 1 T3+, 2 T2+, 3 R1-, 4 T1+, 5 R2-, 6 R3-

## WE-Modular Jack Connectors 615008138021
designator C?
WR-COM Modular Jack RJ45 Vertical; Manufacturer: Würth Elektronik eiSos GmbH; partNo: 615008138021; ComponentLink1 Description: Manufacturer; ComponentLink2 Description: Datasheet; NoPins: 8
footprint 615008138021
pins: 1 DA+, 2 DA-, 3 DB+, 4 DC+, 5 DC-, 6 DB-, 7 DD+, 8 DD-

## WE-Modular Jack Connectors 615008144221
designator C?
WR-COM Modular Jack Vertical Plastic 1x1 TH    8P8C; Manufacturer: Würth Elektronik eiSos GmbH; partNo: 615008144221; ComponentLink1 Description: Manufacturer; ComponentLink2 Description: Datasheet; NoPins: 8
footprint 615008144221
pins: 1 DA+, 2 DA-, 3 DB+, 4 DC+, 5 DC-, 6 DB-, 7 DD+, 8 DD-

## WE-Modular Jack Connectors 634008138121
designator C?
WR-COM Modular Jack RJ45 Vertical SMT; Manufacturer: Würth Elektronik eiSos GmbH; partNo: 634008138121; ComponentLink1 Description: Manufacturer; ComponentLink2 Description: Datasheet; NoPins: 8
footprint 634008138121
pins: 1 DA+, 2 DA-, 3 DB+, 4 DC+, 5 DC-, 6 DB-, 7 DD+, 8 DD-


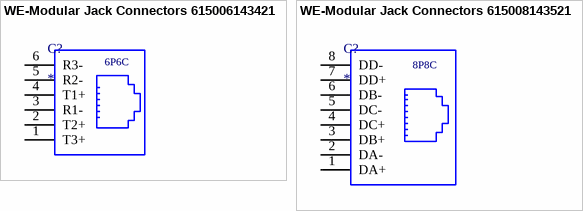
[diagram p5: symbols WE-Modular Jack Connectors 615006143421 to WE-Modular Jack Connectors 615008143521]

## WE-Modular Jack Connectors 615006143421
designator C?
WR-COM Modular Jack Horizontal Half-shielded 1x1 TH    6P6C Tab Down; Manufacturer: Würth Elektronik eiSos GmbH; partNo: 615006143421; ComponentLink1 Description: Manufacturer; ComponentLink2 Description: Datasheet; NoPins: 6
footprint 615006143421
pins: 1 T3+, 2 T2+, 3 R1-, 4 T1+, 5 R2-, 6 R3-

## WE-Modular Jack Connectors 615008143521
designator C?
WR-COM Modular Jack Horizontal Half-shielded 1x1 TH    8P8C Tab Down; Manufacturer: Würth Elektronik eiSos GmbH; partNo: 615008143521; ComponentLink1 Description: Manufacturer; ComponentLink2 Description: Datasheet; NoPins: 8
footprint 615008143521
pins: 1 DA+, 2 DA-, 3 DB+, 4 DC+, 5 DC-, 6 DB-, 7 DD+, 8 DD-


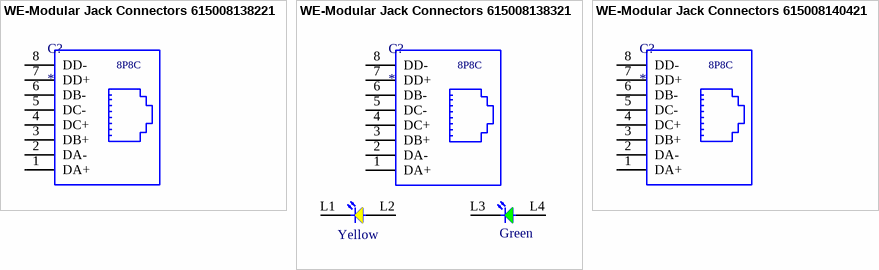
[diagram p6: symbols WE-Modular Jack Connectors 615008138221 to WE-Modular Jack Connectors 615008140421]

## WE-Modular Jack Connectors 615008138221
designator C?
WR-COM Modular Jack RJ45 Vertical  Shielded; Manufacturer: Würth Elektronik eiSos GmbH; partNo: 615008138221; ComponentLink1 Description: Manufacturer; ComponentLink2 Description: Datasheet; NoPins: 8
footprint 615008138221
pins: 1 DA+, 2 DA-, 3 DB+, 4 DC+, 5 DC-, 6 DB-, 7 DD+, 8 DD-

## WE-Modular Jack Connectors 615008138321
designator C?
WR-COM Modular Jack RJ45 Vertical  Shielded  With LED - left yellow - right green; Manufacturer: Würth Elektronik eiSos GmbH; partNo: 615008138321; ComponentLink1 Description: Manufacturer; ComponentLink2 Description: Datasheet; NoPins: 12
footprint 615008138321
pins: 1 DA+, 2 DA-, 3 DB+, 4 DC+, 5 DC-, 6 DB-, 7 DD+, 8 DD-, L1, L2, L3, L4

## WE-Modular Jack Connectors 615008140421
designator C?
WR-COM Modular Jack Vertical Shielded 1x1 TH    8P8C; Manufacturer: Würth Elektronik eiSos GmbH; partNo: 615008140421; ComponentLink1 Description: Manufacturer; ComponentLink2 Description: Datasheet; NoPins: 8
footprint 615008140421
pins: 1 DA+, 2 DA-, 3 DB+, 4 DC+, 5 DC-, 6 DB-, 7 DD+, 8 DD-


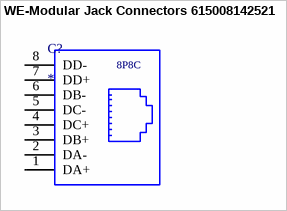
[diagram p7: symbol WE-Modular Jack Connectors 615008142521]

## WE-Modular Jack Connectors 615008142521
designator C?
WR-COM Modular Jack 45° Plastic 1x1 TH    8P8C; Manufacturer: Würth Elektronik eiSos GmbH; partNo: 615008142521; ComponentLink1 Description: Manufacturer; ComponentLink2 Description: Datasheet; NoPins: 8
footprint 615008142521 (45° Plastic 1x1 TH    8P8C)
pins: 1 DA+, 2 DA-, 3 DB+, 4 DC+, 5 DC-, 6 DB-, 7 DD+, 8 DD-


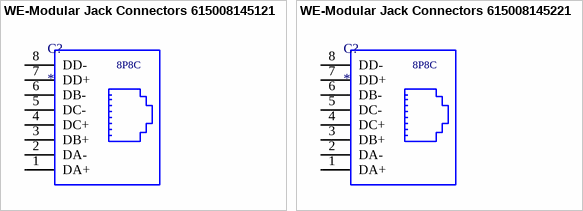
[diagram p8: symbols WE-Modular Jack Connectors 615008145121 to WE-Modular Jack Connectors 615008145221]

## WE-Modular Jack Connectors 615008145121
designator C?
WR-COM Modular Jack 45° Shielded 1x1 TH  8P8C Reverse White; Manufacturer: Würth Elektronik eiSos GmbH; partNo: 615008145121; ComponentLink1 Description: Manufacturer; ComponentLink2 Description: Datasheet; NoPins: 8
footprint 615008145121 (45° Shielded 1x1 TH  8P8C Reverse White)
pins: 1 DA+, 2 DA-, 3 DB+, 4 DC+, 5 DC-, 6 DB-, 7 DD+, 8 DD-

## WE-Modular Jack Connectors 615008145221
designator C?
WR-COM Modular Jack 45° Shielded 1x1 TH  8P8C Standard White; Manufacturer: Würth Elektronik eiSos GmbH; partNo: 615008145221; ComponentLink1 Description: Manufacturer; ComponentLink2 Description: Datasheet; NoPins: 8
footprint 615008145221 (45° Shielded 1x1 TH  8P8C Standard White)
pins: 1 DA+, 2 DA-, 3 DB+, 4 DC+, 5 DC-, 6 DB-, 7 DD+, 8 DD-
